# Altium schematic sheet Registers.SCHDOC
size A4; DocumentNumber: 3; SheetNumber: 3; SheetTotal: 6
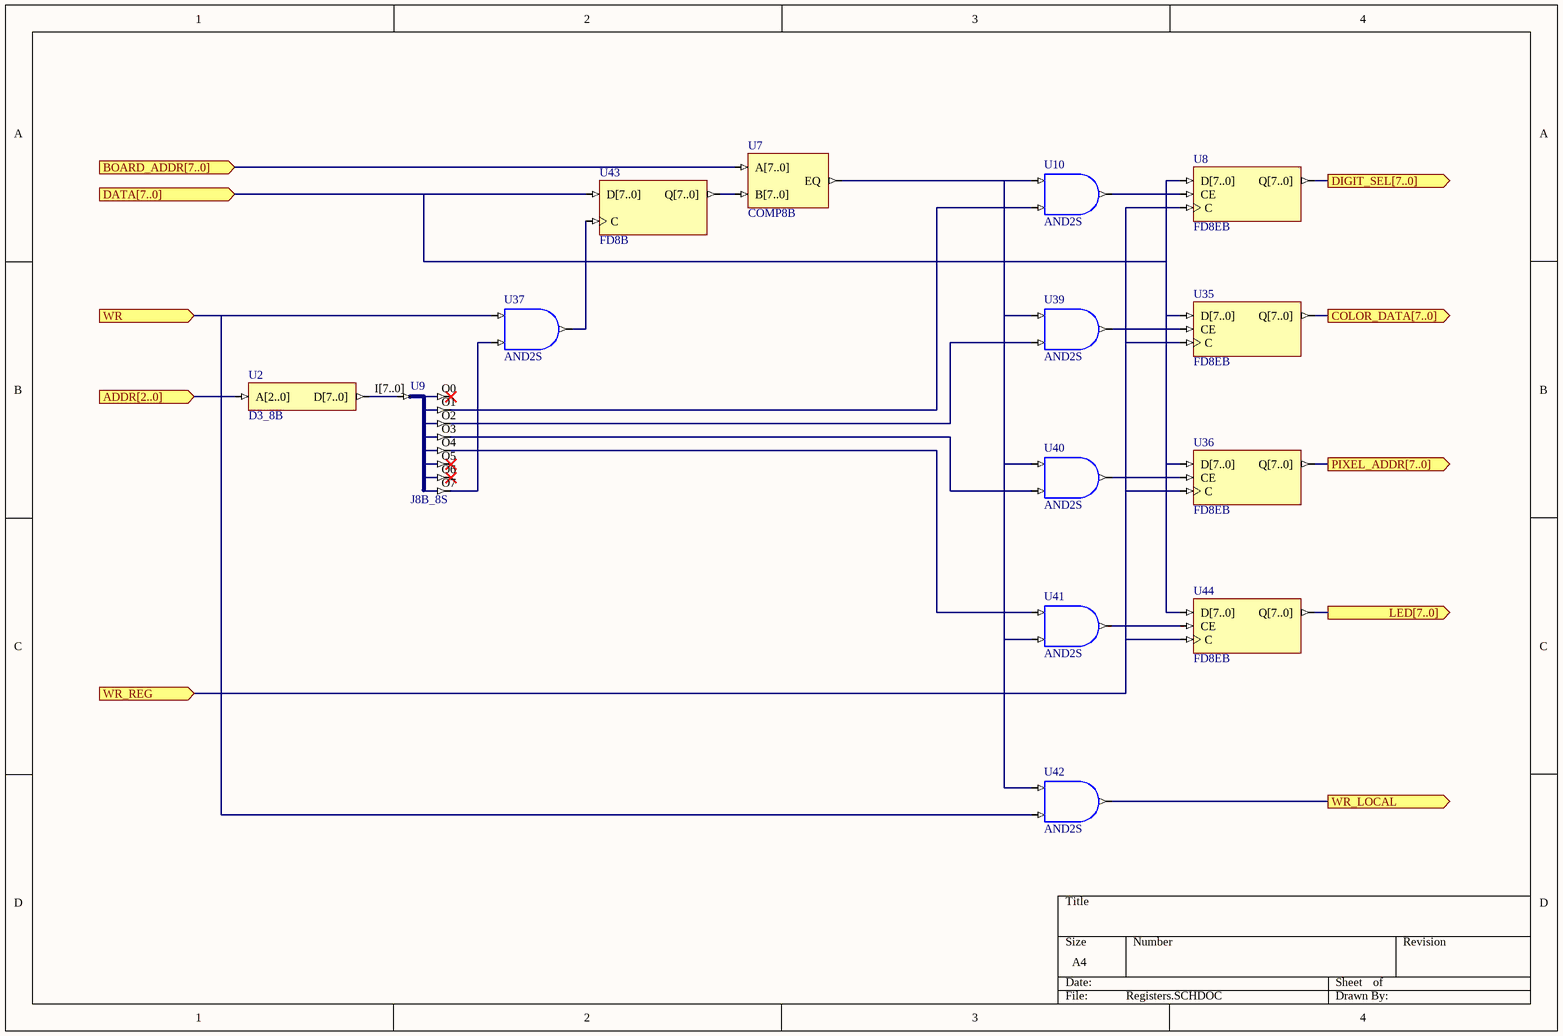
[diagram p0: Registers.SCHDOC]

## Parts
U2  D3_8B
U7  COMP8B
U8  FD8EB
U9  J8B_8S
U10  AND2S
U35  FD8EB
U36  FD8EB
U37  AND2S
U39  AND2S
U40  AND2S
U41  AND2S
U42  AND2S
U43  FD8B
U44  FD8EB

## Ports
ADDR[2..0] (in), BOARD_ADDR[7..0] (in), COLOR_DATA[7..0] (out), DATA[7..0] (in), DIGIT_SEL[7..0] (out), LED[7..0] (out), PIXEL_ADDR[7..0] (out), WR (in), WR_LOCAL (out), WR_REG (in)

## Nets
WR: U37.I0 U42.I1 ; port WR
WR_LOCAL: U42.O ; port WR_LOCAL
WR_REG: U8.C U35.C U36.C U44.C ; port WR_REG
NetU7_EQ: U7.EQ U10.I0 U39.I0 U40.I0 U41.I1 U42.I0
NetU8_CE: U8.CE U10.O
NetU9_O1: U9.O1 U10.I1
NetU9_O2: U9.O2 U39.I1
NetU9_O3: U9.O3 U40.I1
NetU9_O4: U9.O4 U41.I0
NetU9_O7: U9.O7 U37.I1
NetU35_CE: U35.CE U39.O
NetU36_CE: U36.CE U40.O
NetU37_O: U37.O U43.C
NetU41_O: U41.O U44.CE

Not connected (* = marked no-connect by the designer): U2 A[2..0] D[7..0]; U7 A[7..0] B[7..0]; U8 D[7..0] Q[7..0]; U9 I[7..0] O0* O5* O6*; U35 D[7..0] Q[7..0]; U36 D[7..0] Q[7..0]; U43 D[7..0] Q[7..0]; U44 D[7..0] Q[7..0]

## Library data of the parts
U2 = D3_8B: Binary 3- to 8-Bit Decoder, Bus Version; ArchiveName: GENERIC
U7 = COMP8B: 8-Bit Identity Comparator, Bus Version; Xilinx Equivalent: COMP8; ArchiveName: GENERIC
U8 U35 U36 U44 = FD8EB: 8-Bit D Flip-Flop with Clock Enable, Bus Version; ArchiveName: GENERIC
U9 = J8B_8S: 8-Bit input bus to 8 single pin outputs; ArchiveName: GENERIC
U10 U37 U39-U42 = AND2S: 2-Input AND Gate, Single Pin Version; Xilinx Equivalent: AND2; ArchiveName: GENERIC
U43 = FD8B: 8-Bit D-Type Flip-Flop, Bus Version; Xilinx Equivalent: FD8; ArchiveName: GENERIC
